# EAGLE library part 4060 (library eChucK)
14-stage binary/ripple COUNTER
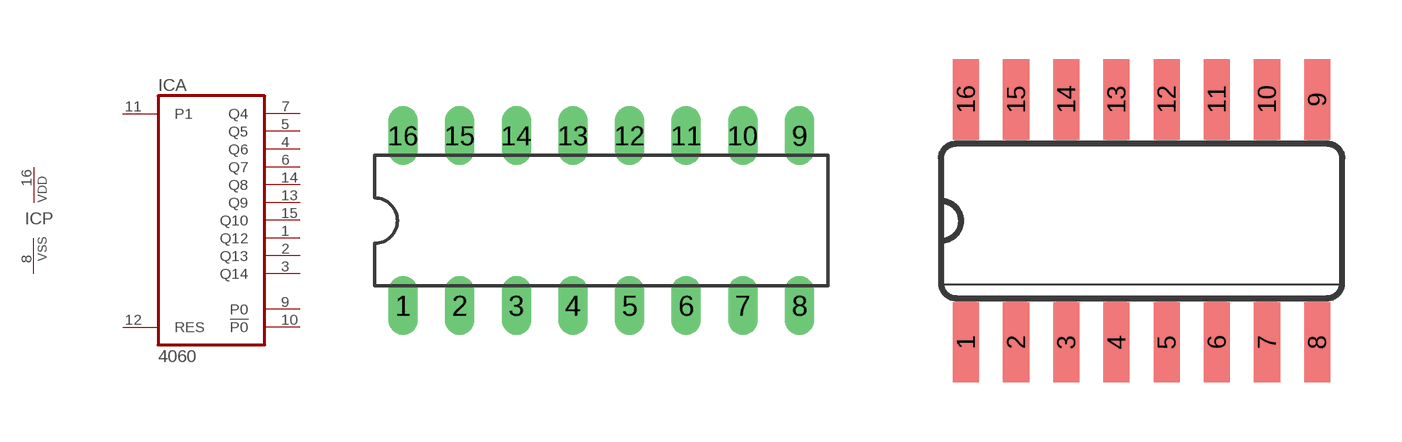
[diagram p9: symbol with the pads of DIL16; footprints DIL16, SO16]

Designator prefix IC; gates A=4060 P=PWRN

## 4060N  [DIL16]
1  A:Q12  out
2  A:Q13  out
3  A:Q14  out
4  A:Q6  out
5  A:Q5  out
6  A:Q7  out
7  A:Q4  out
8  P:VSS  pwr
9  A:P0  out
10  A:!P0  out
11  A:P1  in
12  A:RES  in
13  A:Q9  out
14  A:Q8  out
15  A:Q10  out
16  P:VDD  pwr

## 4060D  [SO16]
Pads as for DIL16

## Footprint DIL16 (pad centres in mm)
Dual In Line Package
drill 0.813 long: 1 -8.89,-3.81; 2 -6.35,-3.81; 3 -3.81,-3.81; 4 -1.27,-3.81; 5 1.27,-3.81; 6 3.81,-3.81; 7 6.35,-3.81; 8 8.89,-3.81; 9 8.89,3.81; 10 6.35,3.81; 11 3.81,3.81; 12 1.27,3.81; 13 -1.27,3.81; 14 -3.81,3.81; 15 -6.35,3.81; 16 -8.89,3.81

## Footprint SO16 (pad centres in mm)
Small Outline package 150 mil
smd 0.66 x 2.032: 1 -4.445,-3.073; 2 -3.175,-3.073; 3 -1.905,-3.073; 4 -0.635,-3.073; 5 0.635,-3.073; 6 1.905,-3.073; 7 3.175,-3.073; 8 4.445,-3.073; 9 4.445,3.073; 10 3.175,3.073; 11 1.905,3.073; 12 0.635,3.073; 13 -0.635,3.073; 14 -1.905,3.073; 15 -3.175,3.073; 16 -4.445,3.073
